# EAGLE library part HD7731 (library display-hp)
LED DISPLAY 1-character 7 segment, decimal point right
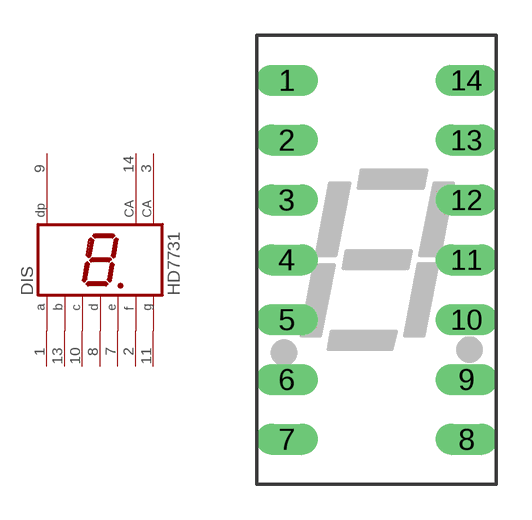
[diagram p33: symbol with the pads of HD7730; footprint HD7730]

Designator prefix DIS

## HD7731 (OC_FARNELL: unknown; OC_NEWARK: unknown)  [HD7730]
1  A  pas
2  F  pas
3  CA  pas
7  E  pas
8  D  pas
9  DP  pas
10  C  pas
11  G  pas
13  B  pas
14  CA  pas

## Footprint HD7730 (pad centres in mm)
LED DISPLAY 8-mm 1 character 7 segment, 2 decimal points
drill 0.813 long: 1 -3.81,7.62; 2 -3.81,5.08; 3 -3.81,2.54; 4 -3.81,0; 5 -3.81,-2.54; 6 -3.81,-5.08; 7 -3.81,-7.62; 8 3.81,-7.62; 9 3.81,-5.08; 10 3.81,-2.54; 11 3.81,0; 12 3.81,2.54; 13 3.81,5.08; 14 3.81,7.62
